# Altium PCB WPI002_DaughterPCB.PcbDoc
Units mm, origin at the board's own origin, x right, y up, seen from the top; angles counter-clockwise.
Board outline 200.66 x 100.33 mm, 2 copper layers (Top layer, Bottom Layer), stack 1.554 mm thick; 8 components, 14 nets, 60 pads, 16 vias.
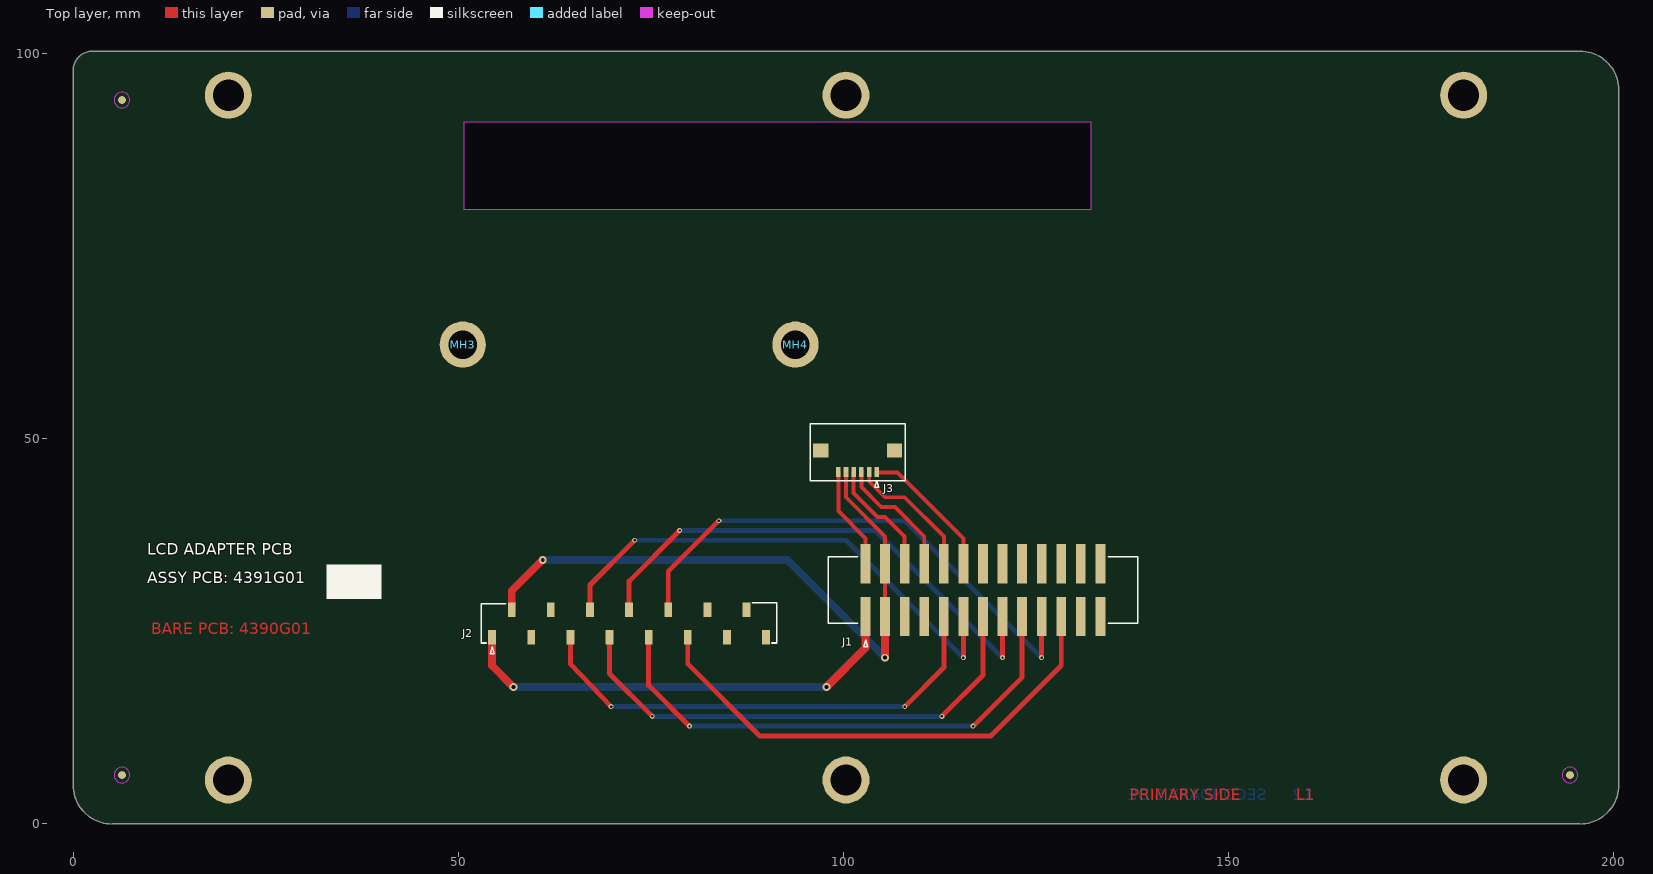
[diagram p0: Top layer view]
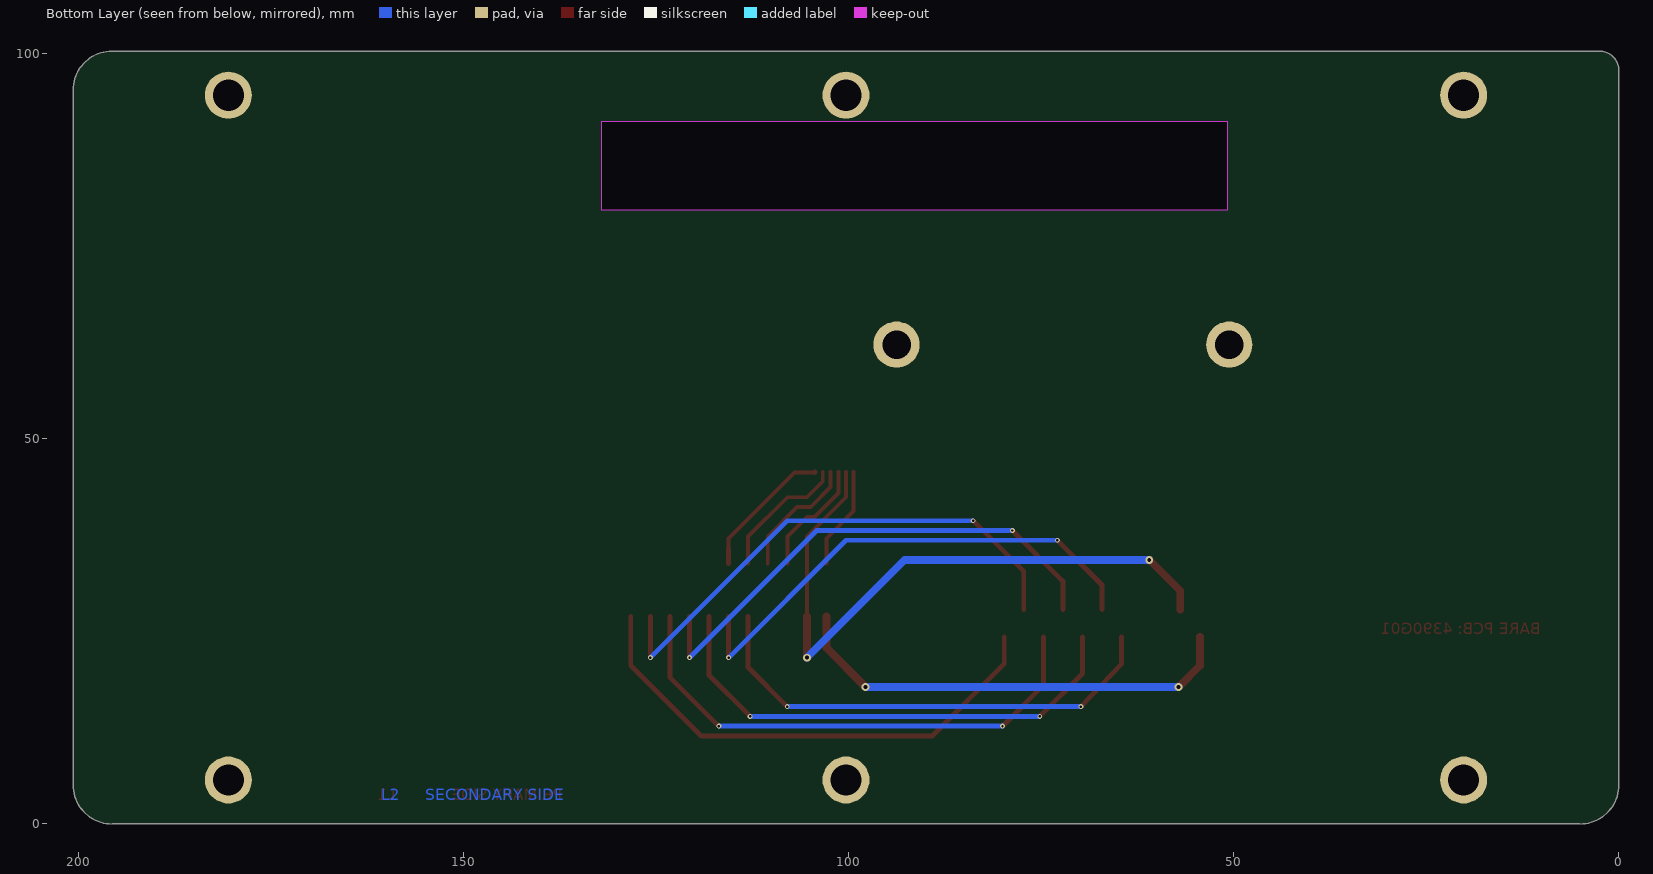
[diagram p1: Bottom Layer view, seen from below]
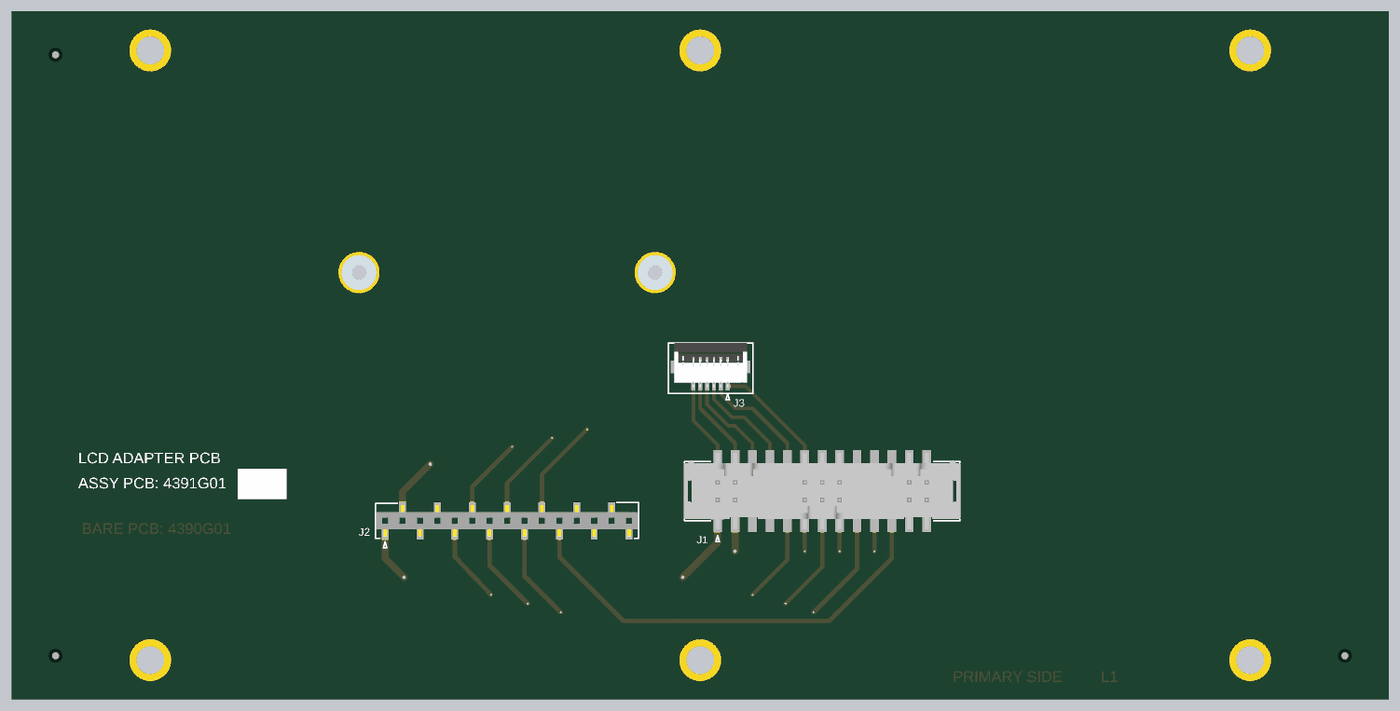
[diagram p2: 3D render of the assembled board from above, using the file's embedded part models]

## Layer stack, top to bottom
Top Solder: solder mask 0.0102, Solder Resist, Dk 3.5
Top layer: signal copper 0.0356
Dielectric 1: core 1.4834, FR-4, Dk 4.2
Bottom Layer: signal copper 0.0356
Bottom Solder: solder mask 0.0102, Solder Resist, Dk 3.5

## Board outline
5.08,0 195.58,0 ccw(c195.58,5.08) 200.66,5.08 200.66,95.25 ccw(c195.58,95.25) 195.58,100.33 2.54,100.33 ccw(c2.54,97.79) 0,97.79 0,5.08 ccw(c5.08,5.08)
cut-out: 50.8,91.186 132.08,91.186 132.08,79.756 50.8,79.756

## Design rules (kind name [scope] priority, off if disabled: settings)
Clearance [All] p1: gap=0.254 ignorepadtopadclearanceinfootprint=FALSE except(0: Arc-Hole Track-Hole SMDPad-Hole THPad-Hole Via-Hole Fill-Hole Poly-Hole Region-Hole Text-Hole)
HoleSize [All] p1: absolutevalues=TRUE maxlimit=7.62 minlimit=0.025 maxpercent=80.000 minpercent=20.000
MinimumSolderMaskSliver [All] p1: minsoldermaskwidth=0.127
PolygonConnect [All] p1: connectstyle=Relief reliefconductorwidth=0.254 reliefentries=4 polygonreliefangle="90 Angle" airgapwidth=0.254
RoutingVias [All] p1: holewidth=0.305 width=0.635 viastyle="Through Hole" minholewidth=0.254 minwidth=0.508 maxholewidth=0.711 maxwidth=1.27
SilkToSolderMaskClearance [IsPad] p1: minsilkscreentomaskgap=0.127 clearancetoexposedcopper=TRUE
SolderMaskExpansion SolderMaskExpansion_1 [ISVIA] p1: expansion=0.102 istentingtop=TRUE
SolderMaskExpansion [All] p2: expansion=0.051 istentingtop=FALSE
Width [All] p1: maxlimit=1.27 minlimit=0.254 preferedwidth=0.381 minimp=50.000000 maximp=50.000000 favimp=50.000000
27 further rules are at their usual default settings.

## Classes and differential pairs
component class LCD_Touch_Breakout: J1 J2 J3 MH3 MH4

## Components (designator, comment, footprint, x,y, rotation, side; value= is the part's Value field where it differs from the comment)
J1 "N2526-6V0C-RB-WE" 3M\N2526-6V0C-RB-WE 118.11,30.353 r0 top locked
J2 "SSM-115-S-SV" SSM-115-S-SV 72.174,26.035 r0 top locked
J3 "686106148922" 686106148922 101.83,45.72 r180 top locked
MH3 "9774100151" 9774100151 50.584,62.23 r0 top
MH4 "9774100151" 9774100151 93.764,62.23 r0 top
? "Comment" FID 6.35,93.98 r0 top
? "Comment" FID 194.31,6.35 r0 top
? "Comment" FID 6.35,6.35 r0 top

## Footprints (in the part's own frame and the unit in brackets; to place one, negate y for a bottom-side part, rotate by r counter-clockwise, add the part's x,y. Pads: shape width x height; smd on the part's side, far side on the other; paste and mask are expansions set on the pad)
3M\N2526-6V0C-RB-WE [mil]
  rect 50x200 smd: 1(-600,-135) 2(-600,135) 3(-500,-135) 4(-500,135) 5(-400,-135) 6(-400,135) 7(-300,-135) 8(-300,135) 9(-200,-135) 10(-200,135) 11(-100,-135) 12(-100,135) 13(0,-135) 14(0,135) 15(100,-135) 16(100,135) 17(200,-135) 18(200,135) 19(300,-135) 20(300,135) 21(400,-135) 22(400,135) 23(500,-135) 24(500,135) 25(600,-135) 26(600,135)
  silkscreen extent -790,-290 790,170, body extent -794,-220 794,220, height 400
9774100151 [mm]
  round 6 hole 3.7: 1(0,0)
  body extent -2.55,-2.55 2.55,2.55, height 10
686106148922 [mm]
  rect 0.6x1.3 smd: 1(-2.5,0) 2(-1.5,0) 3(-0.5,0) 4(0.5,0) 5(1.5,0) 6(2.5,0)
  rect 2x1.8 smd: 7(4.8,-2.75) 8(-4.8,-2.75)
  silkscreen extent -6.17,-6.25 6.12,2.03, body extent -5.3,-6.25 5.3,0.25, height 2.2
FID [mil]
  round 40 smd mask+20: ""(0,0)
  Top layer keep-out circle w1: c0,0 r40
SSM-115-S-SV [mil]
  rect 40x75 smd: 1(-700,-70) 2(-600,70) 3(-500,-70) 4(-400,70) 5(-300,-70) 6(-200,70) 7(-100,-70) 8(0,70) 9(100,-70) 10(200,70) 11(300,-70) 12(400,70) 13(500,-70) 14(600,70) 15(700,-70)
  silkscreen extent -755,-155 755,105, body extent -750,-90 750,90, height 295

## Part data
J1: "CONN HEADER SMD 26POS 2.54MM", Case/Package=Molded, Color=Black, Current Rating=1.75A, Flammability Rating="UL94 V-0", Manufacturer=3M, Max Operating Temperature=105°C, Min Operating Temperature=-55°C, Package Quantity=200, Supplier Part Number 1=MSH26KCT-ND
J2: "CONN RCPT 15POS 0.1 GOLD SMD", Color=Black, Manufacturer=Samtec, Supplier Part Number 1=37J0179
J3: "CONN 1MM HORZ BOTTOM SMD 6POS", Current Rating=1A, Flammability Rating="UL94 V-0", Manufacturer="Wurth Electronics", Max Operating Temperature=105°C, Min Operating Temperature=-40°C, Supplier Part Number 1=732-6017-1-ND, Voltage Rating=100V
MH3 MH4: "RND STNDFF M2.5X0.45 STEEL 10MM", Manufacturer="Wurth Electronics", Manufacturer Part Number=9774100151R, Supplier Part Number 1=732-7117-1-ND

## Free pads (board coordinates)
  round 6.096 hole 4.064: O1(20.161,5.715) O2(20.161,94.615) O3(180.499,5.715) O4(180.499,94.615) O5(100.33,5.715) O6(100.33,94.615)

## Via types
v1: diameter 0.635, hole 0.305, Top layer to Bottom Layer, tented both sides, 12 vias
v2: diameter 1.016, hole 0.508, Top layer to Bottom Layer, tented both sides, 4 vias

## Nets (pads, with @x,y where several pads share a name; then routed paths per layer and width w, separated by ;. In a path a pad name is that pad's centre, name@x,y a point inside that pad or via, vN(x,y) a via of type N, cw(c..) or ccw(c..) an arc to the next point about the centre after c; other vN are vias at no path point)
+3P3V: J1.2 J3.6 | length 13.4
  Top layer w0.508: J3.6 99.33,40.624 102.87,37.084 J1.2
+5V: J1.1 J2.1 | length 59.5
  Top layer w1.016: J2.1 54.394,20.536 v2(57.15,17.78) ; v2(97.79,17.78) 102.87,22.86 J1.1
  Bottom Layer w1.016: v2(57.15,17.78) v2(97.79,17.78)
D0_WAIT: J1.19 J2.10 | length 68.9
  Top layer w0.635: J2.10 77.254,32.804 v1(83.82,39.37) ; v1(125.73,21.59) J1.19
  Bottom Layer w0.635: v1(83.82,39.37) 107.95,39.37 v1(125.73,21.59)
D2_RST: J1.12 J3.1 | length 18.2
  Top layer w0.508: J3.1@104.348,45.639 107.015,45.639 115.57,37.084 J1.12@115.57,35.687
  Top layer w0.635: J3.1 104.33,45.657 J3.1@104.348,45.639 ; J1.12 J1.12@115.57,35.687
D3_RST: J1.17 J2.9 | length 67.4
  Top layer w0.635: J2.9 74.714,17.996 v1(80.01,12.7) ; v1(116.84,12.7) 123.19,19.05 J1.17
  Bottom Layer w0.635: v1(80.01,12.7) v1(116.84,12.7)
D18_INT: J1.21 J2.11 | length 66
  Top layer w0.635: J2.11 79.794,20.79 89.154,11.43 119.126,11.43 128.27,20.574 J1.21
D19_INT: J1.10 J3.2 | length 17.4
  Top layer w0.508: J3.2@103.347,45.702 103.347,44.481 105.41,42.418 107.95,42.418 113.03,37.338 J1.10
D20_SDA: J1.8 J3.3 | length 16.4
  Top layer w0.508: J3.3 102.33,43.72 104.902,41.148 106.68,41.148 110.49,37.338 J1.8
D21_SCL: J1.6 J3.4 | length 15.3
  Top layer w0.508: J3.4 101.33,42.942 104.394,39.878 105.41,39.878 107.95,37.338 J1.6
D50_MISO: J1.11 J2.6 | length 65.7
  Top layer w0.635: J2.6 67.094,31.026 v1(72.898,36.83) ; v1(115.57,21.59) J1.11
  Bottom Layer w0.635: v1(72.898,36.83) 100.33,36.83 v1(115.57,21.59)
D51_MOSI: J1.13 J2.7 | length 65.3
  Top layer w0.635: J2.7 69.634,19.52 v1(75.184,13.97) ; v1(112.776,13.97) 112.776,13.983 118.11,19.317 J1.13
  Bottom Layer w0.635: v1(75.184,13.97) v1(112.776,13.97)
D52_SCK: J1.9 J2.5 | length 63
  Top layer w0.635: J2.5 64.554,20.79 v1(69.85,15.24) ; v1(107.95,15.24) 113.03,20.32 J1.9
  Bottom Layer w0.635: v1(69.85,15.24) v1(107.95,15.24)
D53_CS: J1.15 J2.8 | length 67.1
  Top layer w0.635: J2.8 72.174,31.534 v1(78.74,38.1) ; v1(120.65,21.59) J1.15
  Bottom Layer w0.635: v1(78.74,38.1) 104.14,38.1 v1(120.65,21.59)
GND: J1.3 J1.4 J2.2 J3.5 | length 84.1
  Top layer w0.508: J3.5 100.33,42.418 105.41,37.338 J1.4 J1.3
  Top layer w1.016: J2.2 56.934,30.264 v2(60.96,34.29) ; v2(105.41,21.59) J1.3
  Bottom Layer w1.016: v2(60.96,34.29) 92.71,34.29 v2(105.41,21.59)
pads on no net: ?. J1.5 J1.7 J1.14 J1.16 J1.18 J1.20 J1.22 J1.23 J1.24 J1.25 J1.26 J2.3 J2.4 J2.12 J2.13 J2.14 J2.15 J3.7 J3.8 MH3.1 MH4.1

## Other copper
Top layer:
  text "BARE PCB: 4390G01" at 10.16,24.13 h2.54
  text "PRIMARY SIDE" at 137.16,2.54 h2.54
  text "L1" at 158.75,2.54 h2.54
  text ".Layer_Name" at 104.14,-36.83 h1.52
Bottom Layer:
  text "SECONDARY SIDE" at 154.94,2.54 h2.54
  text "L2" at 160.655,2.54 h2.54
  text ".Layer_Name" at 104.14,-36.83 h1.52

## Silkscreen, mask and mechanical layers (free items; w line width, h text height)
Top Overlay:
  rectangle: 32.893,29.21 40.005,33.655
  text "LCD ADAPTER PCB" at 9.652,34.42 h2.54
  text "ASSY PCB: 4391G01" at 9.652,30.762 h2.54
  text ".Layer_Name" at 104.14,-36.83 h1.52
Bottom Overlay:
  text ".Layer_Name" at 104.14,-36.83 h1.52
Top Paste:
  text ".Layer_Name" at 104.14,-36.83 h1.52
Bottom Paste:
  text ".Layer_Name" at 104.14,-36.83 h1.52
Top Solder:
  text ".Layer_Name" at 104.14,-36.83 h1.52
Bottom Solder:
  text ".Layer_Name" at 104.14,-36.83 h1.52
Mechanical 1:
Mechanical 3:
  circle w0.254: c213.36,-12.7 r1.27
  circle w0.254: c213.36,-12.7 r2.54
  circle w0.254: c-12.7,113.03 r1.27
  circle w0.254: c-12.7,113.03 r2.54
  circle w0.254: c-12.7,-12.7 r2.54
  circle w0.254: c-12.7,-12.7 r1.27
  lines w0.127: 65.307,-33.921 131.347,-33.921 ; 65.307,-29.476 131.347,-29.476 ; 90.707,-39.001 90.707,-24.396 ; 65.307,-39.001 65.307,-24.396 131.347,-24.396 131.347,-39.001 65.307,-39.001
  lines w0.254: -17.78,-12.7 -7.62,-12.7 ; -17.78,113.03 -7.62,113.03 ; -12.7,-17.78 -12.7,-7.62 ; -12.7,107.95 -12.7,118.11 ; 208.28,-12.7 218.44,-12.7 ; 213.36,-17.78 213.36,-7.62 ; 0,5.08 ccw(c5.08,5.08) 5.08,0 195.58,0 ccw(c195.58,5.08) 200.66,5.08 200.66,95.25 ccw(c195.58,95.25) 195.58,100.33 2.54,100.33 ccw(c2.54,97.79) 0,97.79 0,5.08 ; 50.8,79.756 50.8,91.186 132.08,91.186 132.08,79.756 50.8,79.756
  text "TITLE:" at 91.977,-26.301 h1.14
  text "LCD ADAPTER PCB" at 102.235,-27.94 h2.16
  text "DATE:" at 66.577,-31.381 h1.14
  text "PART NO.:" at 91.977,-31.381 h1.14
  text "REV:" at 121.187,-31.381 h1.14
  text "1" at 127.254,-32.563 h1.52
  text "4390G01" at 104.648,-32.69 h2.54
  text ".Print_Date" at 71.022,-33.286 h1.14
  text "FILE NAME:" at 65.942,-35.826 h1.14
  text "LAYER:" at 91.977,-35.826 h1.14
Drill Drawing:
  circle w0.254: c231.791,86 r0.847
  lines w0.254: -11.43,5.715 18.923,5.715 ; -11.43,79.756 49.53,79.756 ; -11.43,91.186 49.53,91.186 ; -11.43,100.33 -1.27,100.33 ; 20.168,-11.43 20.168,4.445 ; 50.8,92.71 50.8,111.76 ; 67.056,-125.222 79.979,-125.043 ; 72.898,-130.123 79.979,-130.123 ; 83.789,-129.488 83.789,-125.678 ; 83.789,-128.218 85.059,-129.488 ; 84.424,-125.678 88.234,-129.488 ; 87.599,-125.678 91.409,-129.488 ; 89.602,-145.121 120.752,-145.161 ; 90.774,-125.678 94.584,-129.488 ; 93.949,-125.678 97.759,-129.488 ; 97.124,-125.678 100.934,-129.488 ; 100.299,-125.678 104.109,-129.488 ; 103.474,-125.678 107.284,-129.488 ; 106.649,-125.678 110.459,-129.488 ; 109.824,-125.678 113.634,-129.488 ; 113.102,-125.678 116.912,-129.488 ; 116.174,-125.678 119.984,-129.488 ; 119.349,-125.678 123.159,-129.488 ; 122.524,-125.678 126.334,-129.488 ; 125.699,-125.678 129.509,-129.488 129.509,-125.678 ; 128.874,-125.678 129.509,-126.313 ; 132.08,92.71 132.08,111.76 ; 133.319,-130.123 134.589,-130.123 ; 133.319,-125.043 134.589,-125.043 ; 200.66,-11.43 200.66,-1.27 ; 201.295,-0.254 200.66,1.27 ; 202.184,0.635 200.66,1.27 ; 219.329,-2.667 219.329,-2.681 219.344,-2.696 204.626,-2.696 200.66,1.27 ; 263.473,65.22 294.588,65.22 ; 0,5.08 ccw(c5.08,5.08) 5.08,0 195.58,0 ccw(c195.58,5.08) 200.66,5.08 200.66,95.25 ccw(c195.58,95.25) 195.58,100.33 2.54,100.33 ccw(c2.54,97.79) 0,97.79 0,5.08 ; 50.8,79.756 50.8,91.186 132.08,91.186 132.08,79.756 50.8,79.756 ; 81.249,-130.758 81.249,-129.488 132.049,-129.488 132.049,-130.758 81.249,-130.758 ; 81.249,-125.678 81.249,-124.408 132.049,-124.408 132.049,-125.678 81.249,-125.678 ; 230.944,88.963 232.638,88.963 232.638,90.657 230.944,90.657 230.944,88.963 ; 230.944,93.197 231.368,93.197 231.791,92.773 232.214,93.197 232.638,93.197 232.214,93.62 232.638,94.043 232.214,94.043 231.791,94.467 231.368,94.043 230.944,94.043 231.368,93.62 230.944,93.197 ; 230.944,98.277 232.638,98.277 231.791,96.584 230.944,98.277
  lines w0.305: -65.792,-111.011 -53.092,-111.011 ; -65.792,-9.411 -53.092,-9.411 ; -65.792,92.189 -53.092,92.189 ; 80.258,-225.311 80.258,-212.611 ; 80.258,193.789 80.258,206.489 ; 213.608,-225.311 213.608,-212.611 ; 213.608,193.789 213.608,206.489 ; 307.588,-212.611 307.588,-154.191 480.308,-154.191 ; 307.588,-207.531 378.708,-207.531 480.308,-207.531 ; 307.588,-202.451 378.708,-202.451 ; 307.588,-197.371 378.708,-197.371 ; 307.588,-192.291 378.708,-192.291 480.308,-192.291 ; 307.588,-187.211 378.708,-187.211 ; 310.763,-177.051 330.448,-177.051 ; 346.958,-225.311 346.958,-212.611 ; 346.958,172.199 480.308,172.199 ; 346.958,177.279 480.308,177.279 ; 346.958,182.359 480.308,182.359 ; 346.958,187.439 480.308,187.439 ; 346.958,206.489 346.958,193.789 346.958,167.119 480.308,167.119 ; 350.641,134.48 362.071,134.48 ; 355.848,-207.404 355.848,-187.211 ; 359.658,167.119 359.658,187.439 ; 378.708,-212.611 378.708,-154.191 ; 378.708,-173.495 480.308,-173.495 ; 393.948,-207.531 393.948,-192.291 ; 409.188,-207.531 409.188,-192.291 ; 429.508,-212.611 429.508,-207.531 ; 430.778,167.119 430.778,187.439 ; 453.638,167.119 453.638,187.439 ; 465.068,-207.531 465.068,-192.291 ; 480.308,-111.011 493.008,-111.011 ; 480.308,-9.411 493.008,-9.411 ; 480.308,92.189 493.008,92.189 ; -53.092,-212.611 -53.092,193.789 480.308,193.789 480.308,-212.611 -53.092,-212.611
  lines w0.381: 229.425,84.01 333.945,84.01 ; 229.425,99.251 333.945,99.251 ; 243.418,80.2 243.418,103.06 ; 257.13,80.2 257.13,103.06 ; 286.332,80.2 286.332,103.06 ; 299.181,80.2 299.181,103.06 ; 317.819,80.2 317.819,103.06 ; 229.425,80.2 333.945,80.2 333.945,103.06 229.425,103.06 229.425,80.2
  lines w0.508: -11.43,0 -1.27,0 ; 0,-11.43 0,-1.27
  text "4" at 12.948,197.599 h3.17
  text "3" at 146.298,197.599 h3.17
  text "2" at 279.648,197.599 h3.17
  text "1" at 412.998,197.599 h3.17
  text "REVISIONS" at 407.283,189.344 h1.91
  text "LTR" at 351.403,183.629 h1.91
  text "DESCRIPTION" at 385.058,183.629 h1.91
  text "DATE" at 438.398,183.629 h1.91
  text "APPROVED" at 458.718,183.629 h1.91
  text "D" at -60.712,141.719 h3.17
  text "D" at 485.388,141.719 h3.17
  text "NOTES" at 350.641,135.75 h2.22
  text "1.  LATEST VERSION OF ALL REFERENCED SPECIFICATIONS TO BE USED UNLESS" at 352.863,129.4 h1.91
  text "OTHERWISE SPECIFIED." at 357.943,124.32 h1.91
  text "2.  FABRICATE IN ACCORDANCE WITH IPC-6012B, CLASS 2  UNLESS" at 352.863,119.24 h1.91
  text "OTHERWISE SPECIFIED." at 357.943,114.16 h1.91
  text "2.000" at 51.943,113.026 h3.81 r90
  text "5.200" at 133.35,113.03 h3.81 r90
  text "3.  INSPECT IN ACCORDANCE WITH IPC-6012B, CLASS 2 UNLESS OTHERWISE" at 352.863,107.81 h1.91
  text "SPECIFIED." at 357.943,102.73 h1.91
  text "Symbol" at 231.712,100.393 h1.83
  text "Count" at 244.561,100.393 h1.83
  text "Hole Size" at 258.273,100.393 h1.83
  text "Plated" at 287.475,100.393 h1.83
  text "Hole Type" at 300.324,100.393 h1.83
  text "Via/Pad" at 318.962,100.393 h1.83
  text "3.950" at -20.701,99.229 h3.81
  text "12" at 244.561,96.584 h1.52
  text "12.00mil (0.305mm)" at 258.273,96.584 h1.52
  text "PTH" at 287.475,96.584 h1.52
  text "Round" at 300.324,96.584 h1.52
  text "Via" at 318.962,96.584 h1.52
  text "4. MATERIAL: HIGH TEMP FR4 (POLYCLAD FR370 OR EQUIVALENT)." at 352.863,96.38 h1.91
  text "4" at 244.561,92.773 h1.52
  text "20.00mil (0.508mm)" at 258.273,92.773 h1.52
  text "PTH" at 287.475,92.773 h1.52
  text "Round" at 300.324,92.773 h1.52
  text "Via" at 318.962,92.773 h1.52
  text "SEE LAYER STACKUP FOR THICKNESS." at 357.943,91.3 h1.91
  text "3.590" at -20.701,89.831 h3.81
  text "2" at 244.561,88.963 h1.52
  text "145.67mil (3.700mm)" at 258.273,88.963 h1.52
  text "PTH" at 287.475,88.963 h1.52
  text "Round" at 300.324,88.963 h1.52
  text "Pad" at 318.962,88.963 h1.52
  text "FINISHED BOARD MUST MEET UL94V-0." at 358.261,86.22 h1.91
  text "6" at 244.561,85.153 h1.52
  text "160.00mil (4.064mm)" at 258.273,85.153 h1.52
  text "PTH" at 287.475,85.153 h1.52
  text "Round" at 300.324,85.153 h1.52
  text "Pad" at 318.962,85.153 h1.52
  text "CUT-OUT" at 81.915,83.876 h5.08
  text "24 Total" at 244.561,81.343 h1.52
  text "5.  PLATED-THRU HOLES TO HAVE A MINIMUM COPPER WALL THICKNESS DETERMINED" at 352.927,80.886 h1.91
  text "3.140" at -21.082,78.528 h3.81
  text "BY IPC-6012B, CLASS 2." at 358.007,75.806 h1.91
  text "6.  SILKSCREEN NOMENCLATURE NOT TO COVER ANY PORTION OF A COMPONENT" at 352.927,70.726 h1.91
  text "DRILL TOLERANCES:" at 264.108,65.855 h1.91
  text "PAD. FABRICATOR TO CLIP ANY NON-CONFORMING SILKSCREEN NOMENCLATURE." at 358.007,65.646 h1.91
  text "VIA(S): +.000/-DRILL SIZE" at 264.108,60.775 h1.91
  text "DO NOT REMOVE SILKSCREEN FROM TENTED VIAS." at 357.372,60.566 h1.91
  text "NON-PLATED HOLES: +/-.002" at 264.108,55.695 h1.91
  text "7. UL LOGO AND DATE CODE & VENDOR CODE MUST APPEAR IN ETCH ON PRIMARY" at 352.927,54.851 h1.91
  text "PLATED HOLES: +/-.003" at 264.108,50.615 h1.91
  text "SIDE. SECONDARY SIDE IS ACCEPTABLE IF THERE IS NO ROOM ON PRIMARY SIDE." at 357.372,49.771 h1.91
  text "8.  USE LPI SOLDER MASK (BLACK) OVER BARE COPPER PER IPC-SM-840C, CLASS 2." at 352.927,43.421 h1.91
  text "C" at -60.712,40.119 h3.17
  text "C" at 485.705,38.849 h3.17
  text "9.  SOLDER MASK SHALL BE CAPABLE OF FIVE SOLDER EXPOSURES AT 500" at 352.927,36.436 h1.91
  text "DEGREES F." at 358.007,31.356 h1.91
  text "10.  TOOLING HOLES MUST BE PRIMARY DRILLED AT THE SAME TIME AS" at 352.927,25.641 h1.91
  text "PLATED-THRU HOLES. ALL HOLES MUST BE WITHIN 0.003\" OF RADIAL" at 358.007,20.561 h1.91
  text "TRUE POSITION." at 358.642,15.481 h1.91
  text "11.  DIMENSIONAL TOLERANCES ON PCB ARE AS FOLLOWS UNLESS OTHERWISE" at 352.927,10.401 h1.91
  text "SPECIFIED." at 360.547,5.321 h1.91
  text ".225" at -18.415,4.36 h3.81
  text "HOLE TO HOLE +/-.005\"" at 385.312,3.416 h1.91
  text "0" at -14.605,-1.475 h4.44
  text "HOLE TO EDGE +/-.010\"" at 385.312,-1.664 h1.91
  text "RADIUS .200" at 221.107,-3.895 h3.81
  text "EDGE TO EDGE +/-.010\"" at 385.312,-6.744 h1.91
  text "12.  PADS MUST BE FINISHED TO WITHIN +/-.0015\" OF THE MINOR DIMENSION" at 352.927,-12.459 h1.91
  text "0" at 1.475,-14.478 h4.44 r90
  text "(PAD WIDTH) & +/-0.002\" OF THE MAJOR DIMENSION (PAD LENGTH)." at 358.007,-17.539 h1.91
  text ".794" at 21.167,-18.669 h3.81 r90
  text "7.900" at 201.803,-21.082 h3.81 r90
  text "13.  GLOBAL AND LOCAL FIDUCIALS MUST BE FREE OF ANY MARKINGS." at 352.927,-25.159 h1.91
  text "14. FULL NETLIST TESTING REQUIRED UNLESS OTHERWISE SPECIFIED. TESTING" at 352.927,-32.779 h1.91
  text ".Layer_Name" at 104.14,-36.83 h1.52
  text "SHOULD CONFORM TO IPC-9252." at 360.547,-37.859 h1.91
  text "15. REMOVAL OF NON-FUNCTIONAL PADS ON INNER LAYERS ALLOWED." at 352.927,-42.939 h1.91
  text "16. THEIVING OF OUTER LAYERS IS ACCEPTABLE AS LONG AS THE COPPER IS" at 352.927,-50.559 h1.91
  text "KEPT A MININMUM OF 0.200\" FROM ANY DESIGN FEATURE." at 360.547,-55.639 h1.91
  text "17. PRIOR TO BOARD FABRICATION, COMPARE GERBER DATA TO SUPPLIED" at 352.927,-60.719 h1.91
  text "B" at -60.712,-62.751 h3.17
  text "B" at 485.388,-62.751 h3.17
  text "IPC-D-356A NETLIST. REPORT ALL DISCREPANCIES." at 360.547,-65.799 h1.91
  text "18. ENTIRE BOARD TO BE IMMERSION GOLD PLATED. 2 TO 5 MICROINCHES" at 352.927,-72.149 h1.91
  text "OVER 100 MICROINCHES MINIMUM OF ELECTROLESS NICKEL." at 359.023,-77.229 h1.91
  text "19. BOARD TO BE ROHS COMPLIANT." at 353.181,-82.69 h1.91
  text "0VERALL THICKNESS 0.062 +/-.007" at 81.28,-119.126 h2.22
  text "LAYER 1/PRIMARY SIDE" at 34.259,-126.313 h1.91
  text "COPPER WT=1/2 OZ.*" at 135.859,-126.313 h1.91
  text "LAYER 2/SECONDARY SIDE" at 34.259,-131.393 h1.91
  text "COPPER WT=1/2 OZ.*" at 135.859,-131.393 h1.91
  text "* PRIOR TO PLATING" at 92.177,-138.176 h1.91
  text "LAYER STACKUP" at 91.189,-143.787 h2.54
  text "SCALE:  NONE" at 94.999,-149.502 h1.91
  text "UNLESS OTHERWISE SPECIFIED:" at 310.763,-159.144 h1.91
  text "Boston Engineering Corporation" at 397.485,-159.969 h3.17
  text "A" at -60.712,-163.081 h3.17
  text "A" at 485.388,-163.081 h3.17
  text "DIMENSIONS ARE IN INCHES AND APPLY" at 310.128,-164.859 h1.91
  text "300 BEAR HILL RD." at 421.361,-166.141 h1.91
  text "AFTER PROCESSING TOLERANCES." at 310.128,-168.669 h1.91
  text "Waltham, MA 02451" at 420.98,-170.764 h1.91
  text "TOLERANCES" at 310.763,-175.654 h1.91
  text "TITLE" at 381.248,-178.321 h1.91
  text "+" at 360.928,-179.464 h1.27
  text "+" at 322.828,-180.099 h1.27
  text ".XXX" at 348.863,-180.734 h1.91
  text "-" at 360.928,-180.734 h1.27
  text ".005" at 365.373,-180.734 h1.91
  text ".X" at 312.668,-181.369 h1.91
  text "-" at 322.828,-181.369 h1.27
  text ".1" at 327.908,-181.369 h1.91
  text "LCD ADAPTER PCB" at 412.115,-182.245 h2.54
  text "+" at 322.828,-183.909 h1.27
  text "+" at 360.928,-183.909 h1.27
  text "2" at 366.008,-184.544 h1.91
  text ".XX" at 312.668,-185.179 h1.91
  text "-" at 322.828,-185.179 h1.27
  text ".01" at 327.908,-185.179 h1.91
  text "ANGLES" at 345.688,-185.179 h1.91
  text "-" at 360.928,-185.179 h1.27
  text "FABRICATION DRAWING" at 411.963,-188.493 h2.22
  text "06/02/21" at 360.401,-190.652 h1.52
  text "DRAWN" at 310.128,-191.021 h1.91
  text "IDESIGN" at 326.003,-191.021 h1.52
  text "CHECKED" at 310.128,-196.101 h1.91
  text "SYM" at 383.153,-196.736 h1.91
  text "SIZE" at 397.758,-196.736 h1.91
  text "DRAWING NO." at 411.728,-196.736 h1.91
  text "REV" at 470.148,-196.736 h1.91
  text "APPROVED" at 310.128,-201.181 h1.91
  text "C" at 399.663,-203.086 h2.54
  text "4390G01" at 426.714,-204.102 h3.17
  text "1" at 472.186,-204.368 h3.17
  text "APPROVED" at 310.128,-206.261 h1.91
  text "REMOVE BURRS AND SHARP EDGES" at 314.573,-211.214 h1.91
  text "SCALE" at 380.613,-211.341 h1.91
  text "SHEET" at 433,-211.341 h1.91
  text "1/1" at 398.266,-211.595 h2.22
  text "OF" at 460.496,-211.595 h1.91
  text "1" at 455.517,-211.722 h2.22
  text "1" at 467.582,-211.849 h2.22
  text "4" at 12.948,-221.501 h3.17
  text "3" at 146.298,-221.501 h3.17
  text "2" at 279.648,-221.501 h3.17
  text "1" at 414.268,-221.501 h3.17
